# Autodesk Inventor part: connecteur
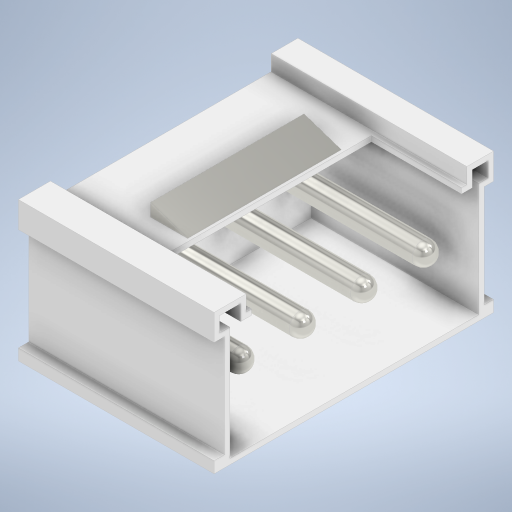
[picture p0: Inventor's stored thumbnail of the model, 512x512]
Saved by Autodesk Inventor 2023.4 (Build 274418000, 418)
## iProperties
Created: 2022-12
Part Number: connecteur
Material: Générique
Document SubType Name: Modeling
Designer: ecuenot
Density: 1 g/cm^3
Appearance: Noir
Author: ecuenot
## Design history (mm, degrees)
node "Plan de construction4"
sketch "Esquisse31"
  geometry: L1 (5.042, 0.463)-(-4.958, 0.463); L2 (4.085, 4.902)-(-3.812, 4.902); L3 (-3.812, 4.902)-(-3.812, 5.463); L4 (4.085, 5.463)-(4.085, 4.902); L5 (-4.958, 5.463)-(-3.812, 5.463); L6 (4.085, 5.463)-(5.042, 5.463); L7 (5.229, 0.868)-(4.706, 0.868); L8 (4.706, 0.868)-(4.706, 4.53); L9 (4.706, 4.53)-(5.229, 4.53); L10 (-4.585, 0.868)-(-5.157, 0.868); L11 (-5.157, 4.53)-(-4.585, 4.53); L12 (-4.585, 4.53)-(-4.585, 0.868); L13 (-4.958, 0.463)-(-4.958, 0.868); L14 (-4.958, 4.53)-(-4.958, 5.463); L15 (5.042, 5.463)-(5.042, 4.53); L16 (5.042, 0.868)-(5.042, 0.463); 6 further points
  constraints: 32 end point, 9 parallel, 6 point on line, 4 horizontal, 4 perpendicular, 1 other
  dimensions: "d212" = 5 distance of L1.end L5.start
extrude "Extrusion22" join sketch "Esquisse31" distance "d221" = 7; taper "d222" = 0 deg
sketch "Esquisse33"
  geometry: L1 (-4.958, 5.463)-(-4.958, 4.53) reference; L2 (-4.958, 4.53)-(-4.585, 4.53) reference; L3 (-4.585, 4.53)-(-4.585, 0.868) reference; L4 (-4.585, 0.868)-(-4.958, 0.868) reference; L5 (-4.958, 0.868)-(-4.958, 0.463) reference; L6 (-4.958, 0.463)-(5.042, 0.463) reference; L7 (5.042, 0.463)-(5.042, 0.868) reference; L8 (5.042, 0.868)-(4.706, 0.868) reference; L9 (4.706, 0.868)-(4.706, 4.53) reference; L10 (4.706, 4.53)-(5.042, 4.53) reference; L11 (5.042, 4.53)-(5.042, 5.463) reference; L12 (5.042, 5.463)-(4.085, 5.463) reference; L13 (4.085, 5.463)-(4.085, 4.902) reference; L14 (4.085, 4.902)-(-3.812, 4.902) reference; L15 (-3.812, 4.902)-(-3.812, 5.463) reference; L16 (-3.812, 5.463)-(-4.958, 5.463) reference; L17 (4.511, 0.659)-(-4.39, 0.659); L18 (-4.39, 0.659)-(-4.39, 4.726); L19 (-4.39, 4.726)-(-4.763, 4.726); L20 (-4.763, 4.726)-(-4.763, 5.268); L21 (-4.763, 5.268)-(-4.007, 5.268); L22 (-4.007, 5.268)-(-4.007, 4.707); L23 (-4.007, 4.707)-(4.28, 4.707); L24 (4.28, 4.707)-(4.28, 5.268); L25 (4.28, 5.268)-(4.847, 5.268); L26 (4.847, 5.268)-(4.847, 4.726); L27 (4.847, 4.726)-(4.511, 4.726); L28 (4.511, 4.726)-(4.511, 0.659); 1 further point
  constraints: 24 end point, 11 other
extrude "Extrusion24" cut sketch "Esquisse33" distance "d226" = 6; taper "d227" = 0 deg
node "Plan de construction5"
sketch "Esquisse34"
  geometry: L1 (8.078, 7.709)-(3.775, 7.709); L2 (3.775, 7.709)-(3.775, 0.199); L3 (3.775, 0.199)-(8.078, 0.199); L4 (8.078, 0.199)-(8.078, 7.709); 1 further point
  constraints: 8 end point, 2 parallel, 1 horizontal, 1 perpendicular
extrude "Extrusion25" cut sketch "Esquisse34" distance "d228" = 2; taper "d229" = 0 deg
node "Plan de construction1"
sketch "Esquisse35"
  geometry: L1 (-3.775, 0)-(3.225, 0) reference; L2 (0.003, 0)-(-1.41, 0.473); L3 (-1.41, 0.473)-(-1.41, 0.026); L4 (-3.775, 0.561)-(3.225, 0.561) reference; L5 (-1.41, 0.026)-(-0.074, 0.026); 1 further point
  constraints: 6 end point, 2 point on line, 1 perpendicular
extrude "Extrusion26" join sketch "Esquisse35" distance "d231" = 5.5; taper "d232" = 0 deg
node "Plan de construction6"
sketch "Esquisse36" dims "d239" = 10
  geometry: L1 (4.511, 4.726)-(4.511, 0.659) reference; L2 (4.511, 2.692)-(-4.39, 2.692); L3 (-4.39, 0.659)-(-4.39, 4.726) reference; C1 r 0.4 at (3.423, 2.692); C2 r 0.4 at (1.223, 2.692); C3 r 0.4 at (-0.977, 2.692); C4 r 0.4 at (-3.177, 2.692); 1 further point
  constraints: 4 centre point, 2 end point, 2 midpoint, 1 horizontal
  dimensions: "d233" = 0.8 diameter of C1; "d236" = 2.2 distance of C1.centre C2.centre
extrude "Extrusion27" join sketch "Esquisse36" distance "d241" = 5.5; taper "d242" = 0 deg
node "Plan de construction2"
fillet "Congé4" dims "d254" = 0.4
node "Plan de construction8"
node "Plan de construction9"
node "Plan de construction7"
sketch "Esquisse41"
  geometry: L1 (12.951, 9.533)-(10.938, 7.52); L2 (10.938, 7.52)-(7.1, 7.52); L3 (7.1, 7.52)-(4.866, 9.533); L4 (4.866, 9.533)-(12.951, 9.533); L5 (12.951, 9.533)-(4.866, 9.533); L6 (-5.186, 9.533)-(-12.812, 9.533); L7 (-12.812, 9.533)-(-10.799, 7.52); L8 (-10.799, 7.52)-(-7.199, 7.52); L9 (-7.199, 7.52)-(-5.186, 9.533); 2 further points
  constraints: 18 end point, 4 point on line, 2 parallel, 1 horizontal, 1 perpendicular
extrude "Extrusion29" cut sketch "Esquisse41" distance "d347" = 5.5; taper "d348" = 0 deg
node "Solide1"
node "Boucle projetée2"
other parameters: "d213" = 5, "d214" = 5
